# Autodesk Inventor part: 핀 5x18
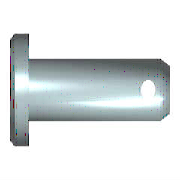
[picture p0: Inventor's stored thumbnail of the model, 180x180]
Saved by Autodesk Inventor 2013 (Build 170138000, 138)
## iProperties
Created: 2012-02
Part Number: 핀 5x18
Material: 강철
Description: 머리가 있는 클레비스 핀
Document SubType Name: Modeling
Standard: ISO 2341
Designer: test
Standard Revision: Second edition 1986-11-01
Standards Organization: ISO
Language: ko-KR
Size Designation: B - 5 x 18
Categories: <MemberInstance><Categories><Category DisplayName="조임쇠" InternalName="e4da775c-781d-43d5-af7c-5136215cf5a6" Mnemonic="FSTN"><Category DisplayName="핀" InternalNa
Density: 7.85 g/cm^3
IsCustomPart: 1
Author: test
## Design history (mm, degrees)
sketch "스케치1"
  geometry: L1 (-1.6, 0)-(-1.6, 4); L2 (-1.6, 4)-(0, 4); L3 (0, 4)-(0, 2.5); L4 (0, 2.5)-(18, 2.5); L5 (18, 2.5)-(18, 0); L6 (-1.6, 0)-(18, 0); L7 (-4, 0)-(17, 0) reference; L8 (0, -0.98)-(0, 3.08) reference; C1 r 0.6 at (15.1, 0)
  constraints: 12 end point, 3 parallel, 2 collinear, 2 perpendicular, 1 centre point, 1 point on line, 1 vertical
  dimensions: "d0" = 5 diameter of L4 L6 (= NND); "d1" = 8 diameter of L2 L6 (= KOD); "d2" = 1.6 distance of L1.end L2.end (= KOH); "d3" = 18 distance of L3.end L4.end (= NLG); "d5" = 2.9 distance from line of L5 C1.centre (= DIST); "d6" = 1.2 diameter of C1 (= BOR)
revolve "본체" stored, may be unused: angle "d4" = 90 deg
extrude "구멍" cut sketch "스케치1" stored distance "d7" = 5 (= NND); taper "d8" = 0 deg
workaxis "Work Axis1"
workplane "Work Plane1"
body "Solid1"
chamfer "모따기1" distance "d9" = 1 (= PHH2); stored, may be unused: angle "d10" = 45 deg (= FAWI2), second distance "d16" = 1 (= PHH2)
chamfer "모따기2" distance "d11" = 2 (= PHH1); stored, may be unused: angle "d12" = 30 deg (= FAWI1), second distance "d17" = 2 (= PHH1)
other parameters: "PHH1" = 2 [user parameter; used in 2 equation terms], "PHH2" = 1 [user parameter; used in 2 equation terms], "KOD" = 8 [user parameter; used in 1 equation term], "KOH" = 1.6 [user parameter; used in 1 equation term], "NND" = 5 [user parameter; used in 2 equation terms], "FAWI1" = 30 deg [user parameter; used in 1 equation term], "FAWI2" = 45 deg [user parameter; used in 1 equation term], "DIST" = 2.9 [user parameter; used in 1 equation term], "BOR" = 1.2 [user parameter; used in 1 equation term], "NLG" = 18 [user parameter; used in 1 equation term], "d13" = 0, "d14" = 0, "d27" = 0, "d28" = 0, "d29" = 0, "d30" = 0, "d31" = 0
